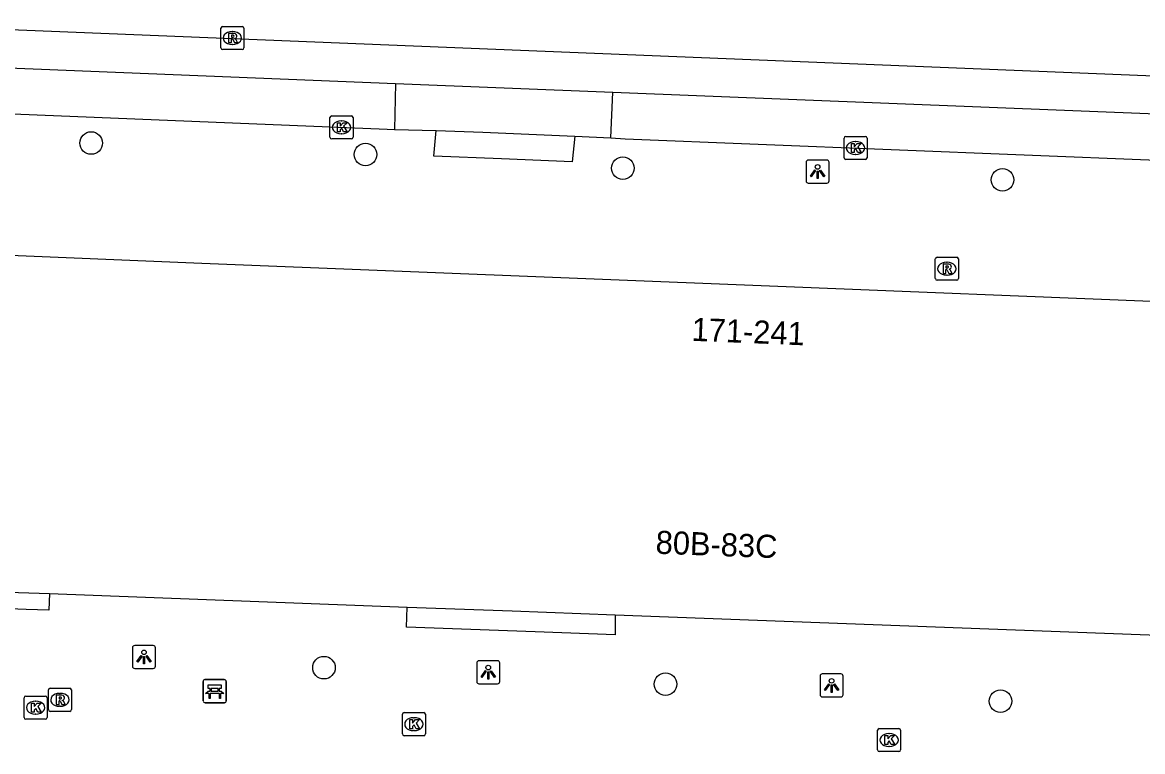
# Model space of a CAD drawing. Extents: x 160891 to 161384, y 386490 to 386907.
# Drawn here: x 161047.88 to 161096.46, y 386872.32 to 386903.93 of the extents above; entities that cross this region are included whole.
import ezdxf

# ---------------------------------------------------------------- set-up
doc = ezdxf.new("R2010")
doc.units = 0
for name, color, linetype in [('IMGEO_Bank', 7, 'Continuous'), ('IMGEO_Boom', 7, 'Continuous'), ('IMGEO_Kolk', 7, 'Continuous'), ('IMGEO_Lichtpunt', 7, 'Continuous'), ('IMGEO_Pand', 7, 'Continuous'), ('IMGEO_Pand_nummerreeks', 7, 'Continuous'), ('IMGEO_Rijbaan_lokaal_gesloten', 7, 'Continuous'), ('IMGEO_Rioolput', 7, 'Continuous'), ('IMGEO_Voetpad_open', 7, 'Continuous')]:
    doc.layers.add(name, color=color, linetype=linetype)

msp = doc.modelspace()

# ---------------------------------------------------------------- linework, layer by layer
at = {"layer": 'IMGEO_Bank'}
for p, q in [((161055.721, 386874.513), (161055.721, 386875.354)), ((161055.721, 386875.354), (161055.721, 386874.513)), ((161055.796, 386875.438), (161056.637, 386875.438)), ((161056.637, 386875.438), (161055.796, 386875.438)), ((161056.362, 386875.056), (161056.08, 386875.056)), ((161056.721, 386875.363), (161056.721, 386874.522)), ((161056.721, 386874.522), (161056.721, 386875.363)), ((161056.418, 386874.836), (161056.025, 386874.836)), ((161056.03, 386874.944), (161056.03, 386875.05)), ((161056.074, 386875.05), (161056.074, 386874.944)), ((161056.08, 386874.938), (161056.362, 386874.938)), ((161056.368, 386874.944), (161056.368, 386875.05)), ((161056.412, 386875.05), (161056.412, 386874.944)), ((161056.646, 386874.438), (161055.805, 386874.438)), ((161055.805, 386874.438), (161056.646, 386874.438))]:
    msp.add_line(p, q, dxfattribs=at)
for points in [[(161056.024, 386875.056), (161055.938, 386875.056), (161055.938, 386875.217), (161056.501, 386875.217), (161056.501, 386875.056), (161056.418, 386875.056)], [(161055.968, 386874.836), (161055.826, 386874.836), (161055.938, 386874.938), (161056.024, 386874.938)], [(161056.018, 386874.829), (161056.018, 386874.622), (161055.975, 386874.622), (161055.975, 386874.829)], [(161056.418, 386874.938), (161056.501, 386874.938), (161056.613, 386874.836), (161056.474, 386874.836)], [(161056.468, 386874.829), (161056.468, 386874.622), (161056.424, 386874.622), (161056.424, 386874.829)]]:
    msp.add_lwpolyline(points, dxfattribs=at)
for centre, radius, start, end in [((161055.799, 386875.36), 0.0779, 92.4484, 184.2845), ((161055.799, 386875.36), 0.0779, 92.4484, 184.2845), ((161056.023, 386875.049), 0.00671, 2.8957, 87.1043), ((161056.08, 386875.049), 0.00671, 92.8957, 177.1043), ((161056.362, 386875.049), 0.00671, 2.8957, 87.1043), ((161056.419, 386875.049), 0.00671, 92.8957, 177.1043), ((161056.643, 386875.36), 0.0779, 2.4484, 94.2845), ((161056.643, 386875.36), 0.0779, 2.4484, 94.2845), ((161055.968, 386874.829), 0.00671, 2.8957, 87.1043), ((161056.025, 386874.829), 0.00671, 92.8957, 177.1043), ((161056.023, 386874.945), 0.00671, 272.8957, 357.1043), ((161056.08, 386874.945), 0.00671, 182.8957, 267.1043), ((161056.362, 386874.945), 0.00671, 272.8957, 357.1043), ((161056.419, 386874.945), 0.00671, 182.8957, 267.1043), ((161056.417, 386874.829), 0.00671, 2.8957, 87.1043), ((161056.474, 386874.829), 0.00671, 92.8957, 177.1043), ((161055.799, 386874.516), 0.0779, 182.4484, 274.2845), ((161055.799, 386874.516), 0.0779, 182.4484, 274.2845), ((161056.643, 386874.516), 0.0779, 272.4484, 4.2845), ((161056.643, 386874.516), 0.0779, 272.4484, 4.2845)]:
    msp.add_arc(centre, radius, start, end, dxfattribs=at)
at = {"layer": 'IMGEO_Boom'}
for centre in [(161050.866, 386898.705), (161062.764, 386898.21), (161073.919, 386897.615), (161090.388, 386897.109), (161060.96, 386875.958), (161075.769, 386875.241), (161090.302, 386874.507)]:
    msp.add_circle(centre, 0.489, dxfattribs=at)
at = {"layer": 'IMGEO_Kolk'}
for p, q in [((161061.296, 386899.884), (161062.148, 386899.884)), ((161061.221, 386898.958), (161061.221, 386899.81)), ((161061.709, 386899.664), (161061.734, 386899.664)), ((161062.222, 386899.81), (161062.222, 386898.958)), ((161062.148, 386898.884), (161061.296, 386898.884)), ((161061.732, 386899.104), (161061.707, 386899.104)), ((161083.515, 386898.066), (161083.515, 386898.918)), ((161083.59, 386898.992), (161084.442, 386898.992)), ((161084.516, 386898.918), (161084.516, 386898.066)), ((161084.003, 386898.772), (161084.028, 386898.772)), ((161084.442, 386897.992), (161083.59, 386897.992)), ((161084.026, 386898.212), (161084.001, 386898.212)), ((161047.954, 386873.797), (161047.954, 386874.649)), ((161048.029, 386874.723), (161048.881, 386874.723)), ((161048.955, 386874.649), (161048.955, 386873.797)), ((161048.442, 386874.503), (161048.467, 386874.503)), ((161048.881, 386873.723), (161048.029, 386873.723)), ((161048.465, 386873.943), (161048.44, 386873.943)), ((161064.36, 386873.083), (161064.36, 386873.935)), ((161064.435, 386874.009), (161065.287, 386874.009)), ((161064.848, 386873.789), (161064.873, 386873.789)), ((161065.361, 386873.935), (161065.361, 386873.083)), ((161064.871, 386873.229), (161064.846, 386873.229)), ((161084.97, 386872.394), (161084.97, 386873.246)), ((161085.045, 386873.32), (161085.897, 386873.32)), ((161085.971, 386873.246), (161085.971, 386872.394)), ((161065.287, 386873.009), (161064.435, 386873.009)), ((161085.458, 386873.1), (161085.483, 386873.1)), ((161085.897, 386872.32), (161085.045, 386872.32)), ((161085.481, 386872.54), (161085.456, 386872.54))]:
    msp.add_line(p, q, dxfattribs=at)
for points in [[(161061.296, 386899.884), (161062.148, 386899.884)], [(161061.221, 386898.958), (161061.221, 386899.81)], [(161061.542, 386899.584), (161061.665, 386899.584), (161061.665, 386899.433), (161061.795, 386899.584), (161061.959, 386899.584), (161061.813, 386899.433), (161061.966, 386899.184), (161061.814, 386899.184), (161061.729, 386899.348), (161061.665, 386899.281), (161061.665, 386899.184), (161061.542, 386899.184), (161061.542, 386899.584)], [(161062.222, 386899.81), (161062.222, 386898.958)], [(161062.148, 386898.884), (161061.296, 386898.884)], [(161083.515, 386898.066), (161083.515, 386898.918)], [(161083.59, 386898.992), (161084.442, 386898.992)], [(161084.516, 386898.918), (161084.516, 386898.066)], [(161083.836, 386898.692), (161083.959, 386898.692), (161083.959, 386898.541), (161084.089, 386898.692), (161084.253, 386898.692), (161084.107, 386898.541), (161084.26, 386898.292), (161084.108, 386898.292), (161084.023, 386898.456), (161083.959, 386898.389), (161083.959, 386898.292), (161083.836, 386898.292), (161083.836, 386898.692)], [(161084.442, 386897.992), (161083.59, 386897.992)], [(161047.954, 386873.797), (161047.954, 386874.649)], [(161048.029, 386874.723), (161048.881, 386874.723)], [(161048.955, 386874.649), (161048.955, 386873.797)], [(161048.275, 386874.423), (161048.398, 386874.423), (161048.398, 386874.272), (161048.528, 386874.423), (161048.692, 386874.423), (161048.546, 386874.272), (161048.699, 386874.023), (161048.547, 386874.023), (161048.462, 386874.187), (161048.398, 386874.12), (161048.398, 386874.023), (161048.275, 386874.023), (161048.275, 386874.423)], [(161048.881, 386873.723), (161048.029, 386873.723)], [(161064.36, 386873.083), (161064.36, 386873.935)], [(161064.435, 386874.009), (161065.287, 386874.009)], [(161064.681, 386873.709), (161064.804, 386873.709), (161064.804, 386873.558), (161064.934, 386873.709), (161065.098, 386873.709), (161064.952, 386873.558), (161065.105, 386873.309), (161064.953, 386873.309), (161064.868, 386873.473), (161064.804, 386873.406), (161064.804, 386873.309), (161064.681, 386873.309), (161064.681, 386873.709)], [(161065.361, 386873.935), (161065.361, 386873.083)], [(161084.97, 386872.394), (161084.97, 386873.246)], [(161085.045, 386873.32), (161085.897, 386873.32)], [(161085.971, 386873.246), (161085.971, 386872.394)], [(161065.287, 386873.009), (161064.435, 386873.009)], [(161085.291, 386873.02), (161085.414, 386873.02), (161085.414, 386872.869), (161085.544, 386873.02), (161085.708, 386873.02), (161085.562, 386872.869), (161085.715, 386872.62), (161085.563, 386872.62), (161085.478, 386872.784), (161085.414, 386872.717), (161085.414, 386872.62), (161085.291, 386872.62), (161085.291, 386873.02)], [(161085.897, 386872.32), (161085.045, 386872.32)]]:
    msp.add_lwpolyline(points, dxfattribs=at)
for centre, start, end in [((161061.298, 386899.808), 91.552, 178.448), ((161061.298, 386899.808), 91.552, 178.448), ((161062.146, 386899.808), 1.552, 88.448), ((161062.146, 386899.808), 1.552, 88.448), ((161061.298, 386898.96), 181.552, 268.448), ((161061.298, 386898.96), 181.552, 268.448), ((161062.146, 386898.96), 271.552, 358.448), ((161062.146, 386898.96), 271.552, 358.448), ((161083.592, 386898.916), 91.552, 178.448), ((161083.592, 386898.916), 91.552, 178.448), ((161084.44, 386898.916), 1.552, 88.448), ((161084.44, 386898.916), 1.552, 88.448), ((161083.592, 386898.068), 181.552, 268.448), ((161083.592, 386898.068), 181.552, 268.448), ((161084.44, 386898.068), 271.552, 358.448), ((161084.44, 386898.068), 271.552, 358.448), ((161048.031, 386874.647), 91.552, 178.448), ((161048.031, 386874.647), 91.552, 178.448), ((161048.879, 386874.647), 1.552, 88.448), ((161048.879, 386874.647), 1.552, 88.448), ((161048.031, 386873.799), 181.552, 268.448), ((161048.031, 386873.799), 181.552, 268.448), ((161048.879, 386873.799), 271.552, 358.448), ((161048.879, 386873.799), 271.552, 358.448), ((161064.437, 386873.933), 91.552, 178.448), ((161064.437, 386873.933), 91.552, 178.448), ((161065.285, 386873.933), 1.552, 88.448), ((161065.285, 386873.933), 1.552, 88.448), ((161085.047, 386873.244), 91.552, 178.448), ((161085.047, 386873.244), 91.552, 178.448), ((161085.895, 386873.244), 1.552, 88.448), ((161085.895, 386873.244), 1.552, 88.448), ((161064.437, 386873.085), 181.552, 268.448), ((161064.437, 386873.085), 181.552, 268.448), ((161065.285, 386873.085), 271.552, 358.448), ((161065.285, 386873.085), 271.552, 358.448), ((161085.047, 386872.396), 181.552, 268.448), ((161085.047, 386872.396), 181.552, 268.448), ((161085.895, 386872.396), 271.552, 358.448), ((161085.895, 386872.396), 271.552, 358.448)]:
    msp.add_arc(centre, 0.0765, start, end, dxfattribs=at)
for centre, major_axis, ratio, start_param, end_param in [((161061.708, 386899.384), (-0.387, 0.002), 0.722429, 4.712389, 7.853982), ((161061.733, 386899.384), (-0.39, 0.002), 0.717154, 1.570796, 4.712389), ((161084.002, 386898.492), (-0.387, 0.002), 0.722429, 4.712389, 7.853982), ((161084.027, 386898.492), (-0.39, 0.002), 0.717154, 1.570796, 4.712389), ((161048.441, 386874.223), (-0.387, 0.002), 0.722429, 4.712389, 7.853982), ((161048.466, 386874.223), (-0.39, 0.002), 0.717154, 1.570796, 4.712389), ((161064.847, 386873.509), (-0.387, 0.002), 0.722429, 4.712389, 7.853982), ((161064.872, 386873.509), (-0.39, 0.002), 0.717154, 1.570796, 4.712389), ((161085.457, 386872.82), (-0.387, 0.002), 0.722429, 4.712389, 7.853982), ((161085.482, 386872.82), (-0.39, 0.002), 0.717154, 1.570796, 4.712389)]:
    msp.add_ellipse(centre, major_axis=major_axis, ratio=ratio, start_param=start_param, end_param=end_param, dxfattribs=at)
at = {"layer": 'IMGEO_Lichtpunt'}
for p, q in [((161082.772, 386897.967), (161081.964, 386897.967)), ((161082.772, 386897.967), (161081.964, 386897.967)), ((161081.87, 386897.872), (161081.87, 386897.065)), ((161081.87, 386897.872), (161081.87, 386897.065)), ((161082.866, 386897.065), (161082.866, 386897.872)), ((161082.866, 386897.065), (161082.866, 386897.872)), ((161081.964, 386896.971), (161082.772, 386896.971)), ((161081.964, 386896.971), (161082.772, 386896.971)), ((161052.656, 386876.824), (161052.656, 386876.017)), ((161052.656, 386876.824), (161052.656, 386876.017)), ((161053.558, 386876.919), (161052.75, 386876.919)), ((161053.558, 386876.919), (161052.75, 386876.919)), ((161053.652, 386876.017), (161053.652, 386876.824)), ((161053.652, 386876.017), (161053.652, 386876.824)), ((161067.586, 386876.165), (161067.586, 386875.358)), ((161067.586, 386876.165), (161067.586, 386875.358)), ((161068.488, 386876.26), (161067.68, 386876.26)), ((161068.488, 386876.26), (161067.68, 386876.26)), ((161068.582, 386875.358), (161068.582, 386876.165)), ((161068.582, 386875.358), (161068.582, 386876.165)), ((161052.75, 386875.923), (161053.558, 386875.923)), ((161052.75, 386875.923), (161053.558, 386875.923)), ((161082.477, 386875.591), (161082.477, 386874.784)), ((161082.477, 386875.591), (161082.477, 386874.784)), ((161083.379, 386875.686), (161082.571, 386875.686)), ((161083.379, 386875.686), (161082.571, 386875.686)), ((161083.473, 386874.784), (161083.473, 386875.591)), ((161083.473, 386874.784), (161083.473, 386875.591)), ((161067.68, 386875.264), (161068.488, 386875.264)), ((161067.68, 386875.264), (161068.488, 386875.264)), ((161082.571, 386874.69), (161083.379, 386874.69)), ((161082.571, 386874.69), (161083.379, 386874.69))]:
    msp.add_line(p, q, dxfattribs=at)
for points in [[(161082.244, 386897.536), (161082.283, 386897.508), (161082.095, 386897.246), (161082.057, 386897.273), (161082.244, 386897.536)], [(161082.346, 386897.488), (161082.393, 386897.488), (161082.393, 386897.166), (161082.346, 386897.166), (161082.346, 386897.488)], [(161082.456, 386897.508), (161082.494, 386897.535), (161082.681, 386897.273), (161082.642, 386897.245), (161082.456, 386897.508)], [(161053.03, 386876.488), (161053.069, 386876.46), (161052.881, 386876.198), (161052.843, 386876.225), (161053.03, 386876.488)], [(161053.132, 386876.44), (161053.179, 386876.44), (161053.179, 386876.118), (161053.132, 386876.118), (161053.132, 386876.44)], [(161053.242, 386876.46), (161053.28, 386876.487), (161053.467, 386876.225), (161053.428, 386876.197), (161053.242, 386876.46)], [(161067.96, 386875.829), (161067.999, 386875.801), (161067.811, 386875.539), (161067.773, 386875.566), (161067.96, 386875.829)], [(161068.062, 386875.781), (161068.109, 386875.781), (161068.109, 386875.459), (161068.062, 386875.459), (161068.062, 386875.781)], [(161068.172, 386875.801), (161068.21, 386875.828), (161068.397, 386875.566), (161068.358, 386875.538), (161068.172, 386875.801)], [(161082.851, 386875.255), (161082.89, 386875.227), (161082.702, 386874.965), (161082.664, 386874.992), (161082.851, 386875.255)], [(161082.953, 386875.207), (161083, 386875.207), (161083, 386874.885), (161082.953, 386874.885), (161082.953, 386875.207)], [(161083.063, 386875.227), (161083.101, 386875.254), (161083.288, 386874.992), (161083.249, 386874.964), (161083.063, 386875.227)]]:
    msp.add_lwpolyline(points, dxfattribs=at)
for centre in [(161082.369, 386897.67), (161053.155, 386876.622), (161068.085, 386875.963), (161082.976, 386875.389)]:
    msp.add_circle(centre, 0.0994, dxfattribs=at)
for centre, start, end in [((161081.964, 386897.872), 90, 180), ((161081.964, 386897.872), 90, 180), ((161082.772, 386897.872), 0, 90), ((161082.772, 386897.872), 0, 90), ((161081.964, 386897.065), 180, 270), ((161081.964, 386897.065), 180, 270), ((161082.772, 386897.065), 270, 0), ((161082.772, 386897.065), 270, 360), ((161052.75, 386876.824), 90, 180), ((161052.75, 386876.824), 90, 180), ((161053.558, 386876.824), 0, 90), ((161053.558, 386876.824), 0, 90), ((161067.68, 386876.165), 90, 180), ((161067.68, 386876.165), 90, 180), ((161068.488, 386876.165), 0, 90), ((161068.488, 386876.165), 0, 90), ((161052.75, 386876.017), 180, 270), ((161052.75, 386876.017), 180, 270), ((161053.558, 386876.017), 270, 0), ((161053.558, 386876.017), 270, 360), ((161082.571, 386875.591), 90, 180), ((161082.571, 386875.591), 90, 180), ((161083.379, 386875.591), 0, 90), ((161083.379, 386875.591), 0, 90), ((161067.68, 386875.358), 180, 270), ((161067.68, 386875.358), 180, 270), ((161068.488, 386875.358), 270, 0), ((161068.488, 386875.358), 270, 360), ((161082.571, 386874.784), 180, 270), ((161082.571, 386874.784), 180, 270), ((161083.379, 386874.784), 270, 0), ((161083.379, 386874.784), 270, 360)]:
    msp.add_arc(centre, 0.0946, start, end, dxfattribs=at)
at = {"layer": 'IMGEO_Pand'}
for points in [[(161113.143, 386891.17), (161097.194, 386891.813), (161080.645, 386892.481), (161055.667, 386893.489), (161046.293, 386893.867), (161046.299, 386893.997), (161046.043, 386894.008)], [(161073.594, 386878.249), (161112.563, 386876.783), (161112.919, 386885.615), (161113.143, 386891.17)], [(161045.442, 386879.308), (161047.716, 386879.222), (161049.049, 386879.172)], [(161049.049, 386879.172), (161064.569, 386878.588)], [(161064.569, 386878.588), (161069.116, 386878.417), (161073.594, 386878.249)]]:
    msp.add_lwpolyline(points, dxfattribs=at)
at = {"layer": 'IMGEO_Rijbaan_lokaal_gesloten'}
for points in [[(161112.299, 386900.982), (161040.205, 386903.901), (161035.665, 386902.345), (160996.157, 386903.935)], [(161040.028, 386900.281), (161040.12, 386902.25), (161064.059, 386901.284)], [(161064.059, 386901.284), (161064.015, 386899.299)], [(161064.059, 386901.284), (161073.486, 386900.908)], [(161073.403, 386898.925), (161073.486, 386900.908)], [(161073.486, 386900.908), (161109.397, 386899.476), (161112.234, 386899.353)], [(161064.015, 386899.299), (161065.827, 386899.252)], [(161065.827, 386899.252), (161067.845, 386899.171), (161071.838, 386899.01)], [(161071.838, 386899.01), (161073.403, 386898.925)]]:
    msp.add_lwpolyline(points, dxfattribs=at)
at = {"layer": 'IMGEO_Rioolput'}
for p, q in [((161056.561, 386903.757), (161057.413, 386903.757)), ((161056.486, 386902.831), (161056.486, 386903.683)), ((161056.974, 386903.537), (161056.999, 386903.537)), ((161057.487, 386903.683), (161057.487, 386902.831)), ((161057.413, 386902.757), (161056.561, 386902.757)), ((161056.997, 386902.977), (161056.972, 386902.977)), ((161087.475, 386892.828), (161087.475, 386893.68)), ((161087.55, 386893.754), (161088.402, 386893.754)), ((161087.963, 386893.534), (161087.988, 386893.534)), ((161088.476, 386893.68), (161088.476, 386892.828)), ((161088.402, 386892.754), (161087.55, 386892.754)), ((161087.986, 386892.974), (161087.961, 386892.974)), ((161049.083, 386875.064), (161049.935, 386875.064)), ((161049.008, 386874.138), (161049.008, 386874.99)), ((161049.496, 386874.844), (161049.521, 386874.844)), ((161050.009, 386874.99), (161050.009, 386874.138)), ((161049.519, 386874.284), (161049.494, 386874.284)), ((161049.935, 386874.064), (161049.083, 386874.064))]:
    msp.add_line(p, q, dxfattribs=at)
for points in [[(161056.561, 386903.757), (161057.413, 386903.757)], [(161056.486, 386902.831), (161056.486, 386903.683)], [(161057.075, 386903.455), (161056.823, 386903.457), (161056.823, 386903.057)], [(161057.001, 386903.376), (161056.947, 386903.376), (161056.947, 386903.295)], [(161056.947, 386903.295), (161056.999, 386903.295)], [(161057.487, 386903.683), (161057.487, 386902.831)], [(161057.413, 386902.757), (161056.561, 386902.757)], [(161056.823, 386903.057), (161056.947, 386903.057), (161056.947, 386903.219), (161056.958, 386903.219)], [(161057.005, 386903.19), (161057.076, 386903.057), (161057.216, 386903.057), (161057.151, 386903.183)], [(161087.475, 386892.828), (161087.475, 386893.68)], [(161087.55, 386893.754), (161088.402, 386893.754)], [(161088.476, 386893.68), (161088.476, 386892.828)], [(161088.064, 386893.452), (161087.812, 386893.454), (161087.812, 386893.054)], [(161087.812, 386893.054), (161087.936, 386893.054), (161087.936, 386893.216), (161087.947, 386893.216)], [(161087.99, 386893.373), (161087.936, 386893.373), (161087.936, 386893.292)], [(161087.936, 386893.292), (161087.988, 386893.292)], [(161087.994, 386893.187), (161088.065, 386893.054), (161088.205, 386893.054), (161088.14, 386893.18)], [(161088.402, 386892.754), (161087.55, 386892.754)], [(161049.083, 386875.064), (161049.935, 386875.064)], [(161049.008, 386874.138), (161049.008, 386874.99)], [(161049.597, 386874.762), (161049.345, 386874.764), (161049.345, 386874.364)], [(161049.523, 386874.683), (161049.469, 386874.683), (161049.469, 386874.602)], [(161049.469, 386874.602), (161049.521, 386874.602)], [(161050.009, 386874.99), (161050.009, 386874.138)], [(161049.345, 386874.364), (161049.469, 386874.364), (161049.469, 386874.526), (161049.48, 386874.526)], [(161049.527, 386874.497), (161049.598, 386874.364), (161049.738, 386874.364), (161049.673, 386874.49)], [(161049.935, 386874.064), (161049.083, 386874.064)]]:
    msp.add_lwpolyline(points, dxfattribs=at)
for centre, radius, start, end in [((161056.563, 386903.681), 0.0765, 91.552, 178.448), ((161056.563, 386903.681), 0.0765, 91.552, 178.448), ((161057.411, 386903.681), 0.0765, 1.552, 88.448), ((161057.411, 386903.681), 0.0765, 1.552, 88.448), ((161056.983, 386903.484), 0.19, 274.7715, 282.9687), ((161057.007, 386903.28), 0.0964, 77.0061, 93.1865), ((161057.021, 386903.337), 0.0378, 276.6634, 79.6772), ((161057.074, 386903.345), 0.109, 350.3612, 89.416), ((161057.072, 386903.345), 0.112, 277.5842, 350.9817), ((161057.056, 386903.13), 0.108, 29.5134, 73.7905), ((161056.563, 386902.833), 0.0765, 181.552, 268.448), ((161056.563, 386902.833), 0.0765, 181.552, 268.448), ((161056.957, 386903.166), 0.0533, 26.0293, 88.6989), ((161057.411, 386902.833), 0.0765, 271.552, 358.448), ((161057.411, 386902.833), 0.0765, 271.552, 358.448), ((161087.552, 386893.678), 0.0765, 91.552, 178.448), ((161087.552, 386893.678), 0.0765, 91.552, 178.448), ((161088.4, 386893.678), 0.0765, 1.552, 88.448), ((161088.4, 386893.678), 0.0765, 1.552, 88.448), ((161087.946, 386893.163), 0.0533, 26.0293, 88.6989), ((161087.972, 386893.481), 0.19, 274.7715, 282.9687), ((161087.996, 386893.277), 0.0964, 77.0061, 93.1865), ((161088.01, 386893.334), 0.0378, 276.6634, 79.6772), ((161088.063, 386893.342), 0.109, 350.3612, 89.416), ((161088.061, 386893.342), 0.112, 277.5842, 350.9817), ((161088.045, 386893.127), 0.108, 29.5134, 73.7905), ((161087.552, 386892.83), 0.0765, 181.552, 268.448), ((161087.552, 386892.83), 0.0765, 181.552, 268.448), ((161088.4, 386892.83), 0.0765, 271.552, 358.448), ((161088.4, 386892.83), 0.0765, 271.552, 358.448), ((161049.085, 386874.988), 0.0765, 91.552, 178.448), ((161049.085, 386874.988), 0.0765, 91.552, 178.448), ((161049.933, 386874.988), 0.0765, 1.552, 88.448), ((161049.933, 386874.988), 0.0765, 1.552, 88.448), ((161049.505, 386874.791), 0.19, 274.7715, 282.9687), ((161049.529, 386874.587), 0.0964, 77.0061, 93.1865), ((161049.543, 386874.644), 0.0378, 276.6634, 79.6772), ((161049.596, 386874.652), 0.109, 350.3612, 89.416), ((161049.594, 386874.652), 0.112, 277.5842, 350.9817), ((161049.085, 386874.14), 0.0765, 181.552, 268.448), ((161049.085, 386874.14), 0.0765, 181.552, 268.448), ((161049.479, 386874.473), 0.0533, 26.0293, 88.6989), ((161049.578, 386874.437), 0.108, 29.5134, 73.7905), ((161049.933, 386874.14), 0.0765, 271.552, 358.448), ((161049.933, 386874.14), 0.0765, 271.552, 358.448)]:
    msp.add_arc(centre, radius, start, end, dxfattribs=at)
for centre, major_axis, ratio, start_param, end_param in [((161056.973, 386903.257), (-0.387, 0.002), 0.722429, 4.712389, 7.853982), ((161056.998, 386903.257), (-0.39, 0.002), 0.717154, 1.570796, 4.712389), ((161087.962, 386893.254), (-0.387, 0.002), 0.722429, 4.712389, 7.853982), ((161087.987, 386893.254), (-0.39, 0.002), 0.717154, 1.570796, 4.712389), ((161049.495, 386874.564), (-0.387, 0.002), 0.722429, 4.712389, 7.853982), ((161049.52, 386874.564), (-0.39, 0.002), 0.717154, 1.570796, 4.712389)]:
    msp.add_ellipse(centre, major_axis=major_axis, ratio=ratio, start_param=start_param, end_param=end_param, dxfattribs=at)
at = {"layer": 'IMGEO_Voetpad_open'}
for points in [[(161040.028, 386900.281), (161063.696, 386899.307), (161064.015, 386899.299)], [(161071.838, 386899.01), (161071.724, 386897.893), (161068.662, 386898.016), (161065.732, 386898.135), (161065.827, 386899.252)], [(161073.403, 386898.925), (161074.03, 386898.891), (161108.628, 386897.506), (161109.298, 386897.46), (161109.361, 386897.456)], [(161049.049, 386879.172), (161049.023, 386878.446), (161048.048, 386878.482), (161045.473, 386878.577), (161045.442, 386879.308)], [(161073.594, 386878.249), (161073.583, 386877.375), (161070.12, 386877.508), (161064.537, 386877.72), (161064.569, 386878.588)]]:
    msp.add_lwpolyline(points, dxfattribs=at)

# ---------------------------------------------------------------- texts
at = {"layer": 'IMGEO_Pand_nummerreeks'}
for s, rotation, p in [('171-241', 357.691, (161076.887, 386890.131)), ('80B-83C', 357.8629, (161075.332, 386880.902))]:
    msp.add_text(s, height=1, rotation=rotation, dxfattribs=at).set_placement(p)

doc.saveas('drawing.dxf')
